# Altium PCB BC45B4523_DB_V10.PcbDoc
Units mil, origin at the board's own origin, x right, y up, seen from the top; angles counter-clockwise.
Board outline 5409.03 x 2550.03 mil, 2 copper layers (Top Layer, Bottom Layer), stack 62.8 mil thick; 96 components, 59 nets, 275 pads, 147 vias.
Unrouted connection lines stored in the file: 1.
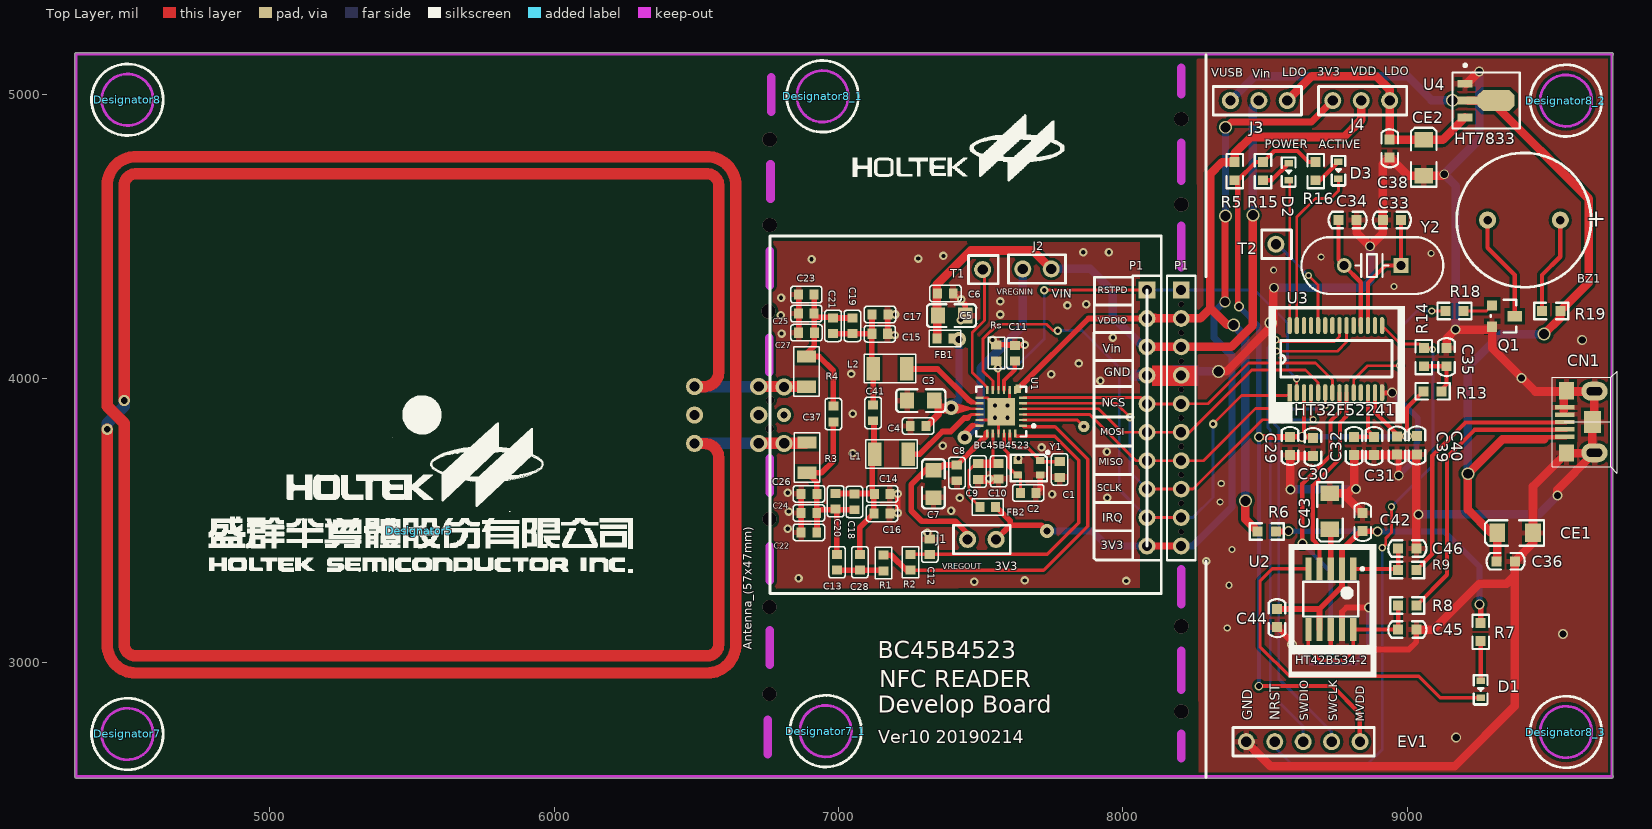
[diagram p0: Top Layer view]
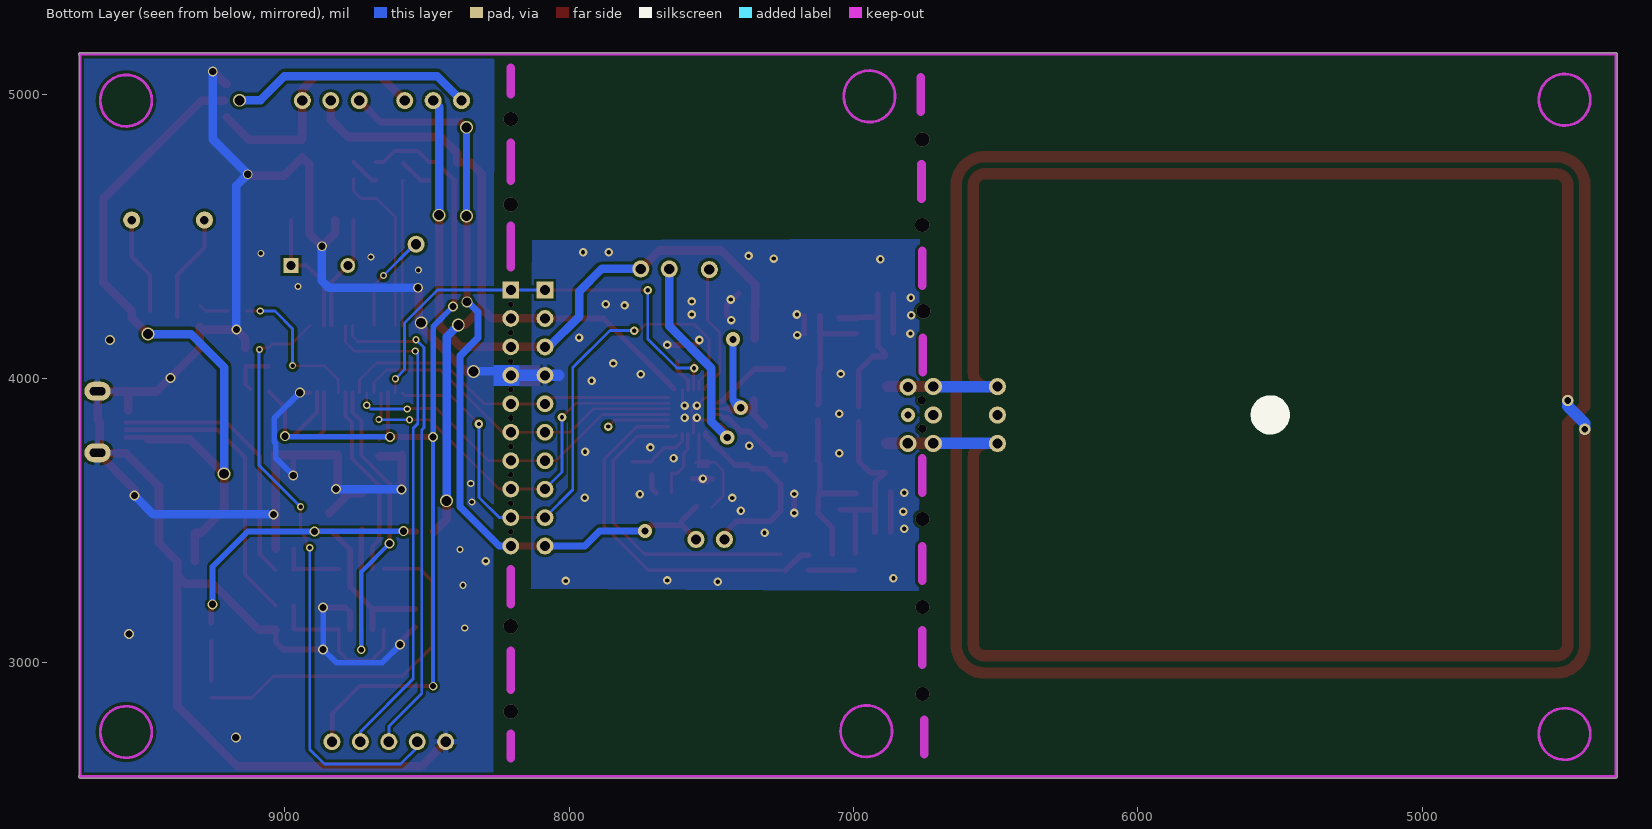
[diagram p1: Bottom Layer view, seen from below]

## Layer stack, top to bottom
Top Layer: signal copper 1.4
Dielectric: core 60, FR-4, Dk 4.6
Bottom Layer: signal copper 1.4

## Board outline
4314.98,2600 ccw(c4320,2600) 4320,2594.99 9719,2594.99 ccw(c9719,2600) 9724.01,2600 ccw(c9719,2600) 9723.01,2603.01 9723.01,5136.99 ccw(c9719,5140) 9724.01,5140 ccw(c9719,5140) 9719,5145.02 4320,5145.02 ccw(c4320,5140) 4314.98,5140

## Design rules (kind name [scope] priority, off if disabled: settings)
Clearance [All] p1: gap=10
Clearance Clearance_Polygon [All vs (InPolygon)] p2: gap=12
Clearance Clearance_Board_Keepout [OnLayer('KeepOutLayer')] p3: gap=20
Clearance Minimum_pad_component_clearcance [(InPadClass('All Pads') AND InComponentClass('All Components')) vs (InPadClass('All Pads') AND InComponentClass('All Components'))] p4: gap=8
Clearance Clearance_DiffPairRouting [(IsTrack AND InDifferentialPairClass('All Differential Pairs')) vs (IsTrack AND InDifferentialPairClass('All Differential Pairs'))] p5: gap=4
Clearance Clearance_Via_Pad [(IsVia) vs (IsPad)] p6: gap=8
Clearance Clearance_Via_Via [(IsVia) vs (IsVia)] p7: gap=8
Clearance Clearance_Default [All] p8: gap=4
ComponentClearance ComponentClearance_1 [All] p2: gap=10 collisioncheckmode=3 verticalgap=10 showdistances=FALSE
DiffPairsRouting DiffPairsRouting_1 [All] p2: maxlimit=10 minlimit=5 mostfreqgap=8 maxuncoupledlength=500
FabricationTestPointUsage FabricationTestPointUsage_1 [All] p2: valid=0 allowmultiple=FALSE
FabricationTestpoint [(IsPad And (OnTopLayer Or OnBottomLayer))] p1: side=3 testpointundercomponent=TRUE minsize=40 maxsize=100 preferedsize=60 minholesize=0 maxholesize=40 preferedholesize=32 testpointgrid=1 allowsidetop=TRUE allowsidebottom=TRUE usegrid=TRUE gridtolerance=0.01
FabricationTestpoint FabricationTestpoint_1 [(IsPad And (OnTopLayer Or OnBottomLayer))] p2: side=3 testpointundercomponent=TRUE minsize=40 maxsize=100 preferedsize=60 minholesize=0 maxholesize=40 preferedholesize=32 testpointgrid=1 allowsidetop=TRUE allowsidebottom=TRUE usegrid=TRUE gridtolerance=0.01
FanoutControl Fanout_LCC [IsLCC] p1: bgadir=Out bgaviamode=Centered fanoutstyle=Auto fanoutdirection=Alternating viagrid=1 // Fanout_LCC (Default Rule)
FanoutControl Fanout_BGA [IsBGA] p2: bgadir=Out bgaviamode=Centered fanoutstyle=Auto fanoutdirection=Alternating viagrid=1 // Fanout_BGA (Default Rule)
FanoutControl Fanout_Default [All] p4: bgadir=Out bgaviamode=Centered fanoutstyle=Auto fanoutdirection=Alternating viagrid=1 // Fanout_Default (Default Rule)
FanoutControl Fanout_Small [(CompPinCount < 5)] p5: bgadir=Out bgaviamode=Centered fanoutstyle=Auto fanoutdirection=OutThenIn viagrid=1 // Fanout_Small (Default Rule)
FanoutControl Fanout_BGA_1 [IsBGA] p6: bgadir=Out bgaviamode=Centered fanoutstyle=Auto fanoutdirection=Alternating viagrid=1 // Fanout_BGA (Default Rule)
FanoutControl Fanout_LCC_1 [IsLCC] p7: bgadir=Out bgaviamode=Centered fanoutstyle=Auto fanoutdirection=Alternating viagrid=1 // Fanout_LCC (Default Rule)
FanoutControl Fanout_SOIC_1 [IsSOIC] p8: bgadir=Out bgaviamode=Centered fanoutstyle=Auto fanoutdirection=Alternating viagrid=1 // Fanout_SOIC (Default Rule)
FanoutControl Fanout_Small_1 [(CompPinCount < 5)] p9: bgadir=Out bgaviamode=Centered fanoutstyle=Auto fanoutdirection=OutThenIn viagrid=1 // Fanout_Small (Default Rule)
FanoutControl Fanout_Default_1 [All] p10: bgadir=Out bgaviamode=Centered fanoutstyle=Auto fanoutdirection=Alternating viagrid=1 // Fanout_Default (Default Rule)
Height Height_1 [All] p2: minheight=0 maxheight=1000 prefheight=500
HoleSize HoleSize_1 [All] p2: absolutevalues=TRUE maxlimit=236.22 minlimit=8 maxpercent=80.000 minpercent=20.000
LayerPairs LayerPairs_1 [All] p2: enforce=TRUE
MinimumAnnularRing [All] p1: minimumring=5
PasteMaskExpansion PasteMaskExpansion_1 [All] p2: expansion=0
PlaneClearance PlaneClearance_1 [All] p2: clearance=10
PlaneConnect PlaneConnect_1 [All] p2: planeconnectstyle=Relief reliefexpansion=20 reliefentries=4 reliefconductorwidth=10 reliefairgap=10
PolygonConnect [IsVia] p1: connectstyle=Direct reliefconductorwidth=10 reliefentries=4 polygonreliefangle="90 Angle" airgapwidth=10
PolygonConnect PolygonConnect_Power [All] p2: connectstyle=Relief reliefconductorwidth=20 reliefentries=4 polygonreliefangle="90 Angle" airgapwidth=10
RoutingCorners RoutingCorners_1 [All] p2: cornerstyle=45-Degree minsetback=100 maxsetback=100
RoutingLayers RoutingLayers_1 [All] p2: top layer_v5=TRUE bottom layer_v5=TRUE
RoutingPriority RoutingPriority_Power [InNetClass('Power')] p2: routingpriority=50
RoutingPriority RoutingPriority_1 [All] p3: routingpriority=0
RoutingTopology RoutingTopology_1 [All] p2: topology=Shortest
RoutingVias [All] p1: holewidth=28 width=50 viastyle="Through Hole" minholewidth=15 minwidth=20 maxholewidth=50 maxwidth=60
RoutingVias RoutingVias_1 [All] p2: holewidth=12 width=22 viastyle="Through Hole" minholewidth=8 minwidth=18 maxholewidth=28 maxwidth=50
ShortCircuit ShortCircuit_1 [All] p2: allowed=FALSE
SilkscreenOverComponentPads [All] p1: minsilkscreentomaskgap=10
SolderMaskExpansion [All] p1: expansion=4
SolderMaskExpansion SolderMaskExpansion_1 [All] p2: expansion=5
UnRoutedNet UnRoutedNet_1 [All] p2:
Width [All] p1: maxlimit=40 minlimit=10 preferedwidth=10 minimp=50.000000 maximp=50.000000 favimp=50.000000
Width Width_Power [InNetClass('Power')] p2: maxlimit=30 minlimit=6 preferedwidth=30
Width Width_All [All] p3: maxlimit=50 minlimit=4 preferedwidth=7 minimp=50.000000 maximp=50.000000 favimp=50.000000
22 further rules are at their usual default settings.

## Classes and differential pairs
component class BC45B4523_DB_Schematic: C1 C2 C3 C4 C5 C6 C7 C8 C9 C10 C11 C12 C13 C14 C15 C16 C17 C18 C19 C20 C21 C22 C23 C24 C25 C26 C27 C28 C37 C41 FB1 FB2 J1 J2 L1 L2 P1 R1 R2 R3 R4 Rs T1 U1 Y1
component class HT32F52241+HT42B534-2: BZ1 C31 C32 C33 C34 C35 C36 C38 C39 C40 C42 C43 C44 C45 C46 CE1 CE2 D1 D2 D3 EV1 J3 J4 Q1 R5 R6 R7 R8 R9 R13 R14 R15 R16 R18 R19 T2 U2 U3 U4 Y2

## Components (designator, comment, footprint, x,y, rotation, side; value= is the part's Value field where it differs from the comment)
BZ1 "Buzzer" BZ 9538,4557 r180 top
C1 "Capacitor SMD" CAPC1608L 7778,3680 r270 top
C2 "Capacitor SMD" CAPC1608L 7667,3598 r0 top
C3 "Capacitor SMD" C0805-2 7343,3922 r180 top
C4 "Capacitor SMD" CAPC1608L 7280,3833 r180 top
C5 "Capacitor SMD" C0805-2 7344,4221 r0 top
C6 "Capacitor SMD" CAPC1608L 7376,4299 r0 top
C7 "Capacitor SMD" C0805-2 7334,3683 r270 top (schematic designator C5)
C8 "Capacitor SMD" CAPC1608L 7416,3668 r270 top (schematic designator C6)
C9 "Capacitor SMD" CAPC1608L 7491.41,3672.93 r270 top
C10 "Capacitor SMD" CAPC1608L 7563.09,3673.92 r270 top
C11 "Capacitor SMD" CAPC1608L 7620.15,4088.65 r90 top
C12 "" CAPC1608L 7321,3408 r270 top
C13 "" CAPC1608L 6995,3354 r270 top
C14 "" CAPC1608L 7153.55,3594 r180 top
C15 "" CAPC1608L 7145.51,4157.15 r0 top
C16 "" CAPC1608L 7153,3526 r180 top
C17 "" CAPC1608L 7146,4225 r0 top
C18 "" CAPC1608L 7056,3566 r270 top
C19 "" CAPC1608L 7049,4185 r90 top
C20 "" CAPC1608L 6990.15,3568 r270 top
C21 "" CAPC1608L 6981,4185 r90 top
C22 "" CAPC1608L 6896,3459 r180 top
C23 "" CAPC1608L 6887,4295 r0 top
C24 "" CAPC1608L 6896,3527 r180 top
C25 "" CAPC1608L 6887,4228 r0 top
C26 "" CAPC1608L 6896.3,3594.43 r0 top
C27 "" CAPC1608L 6887.5,4160.9 r180 top
C28 "" CAPC1608L 7075,3354 r270 top
C29 "0.1uF" C0603-2 8588,3795 r270 top
C30 "" C0603-2 8668,3727 r90 top
C31 "0.1uF(NC)" C0603-2 8883,3795 r270 top
C32 "2.2uF" C0603-2 8813,3795 r270 top
C33 "12pF" C0603-2 8978,4557 r180 top
C34 "12pF" C0603-2 8758,4557 r0 top
C35 "0.1uF" C0603-2 9138,4043 r90 top
C36 "0.1uF" C0603-2 9378,3357 r180 top
C37 "" CAPC1608L 6982,3875 r90 top (schematic designator C19)
C38 "0.1uF" C0603-2 8938,4777 r90 top (schematic designator C36)
C39 "" C0603-2 8964,3732 r90 top (schematic designator C30)
C40 "0.1uF" C0603-2 9034,3797 r270 top (schematic designator C29)
C41 "" CAPC1608L 7122,3879 r270 top (schematic designator C19)
C42 "0.1uF" C0603-2 8843,3463 r90 top
C43 "1uF" C_CASE_A 8728,3472 r90 top
C44 "0.1uF" C0603-2 8542,3189.63 r270 top
C45 "47pF" C0603-2 8968,3117 r0 top
C46 "47pF" C0603-2 8968,3402 r0 top
CE1 "1uF" C_CASE_A 9318,3457 r0 top
CE2 "10uF" C_CASE_A 9058,4837 r270 top (schematic designator CE1)
CN1 "Comment" M-USB-B 9715,3847 r90 top
D1 "LED" LED_SMD0603 9258,2937 r270 top
D2 "Power/RLED" LED_SMD0603 8583,4757 r270 top
D3 "GLED" LED_SMD0603 8758,4762 r270 top
Designator5 "Comment" HOLTEK_MARK 5526,3465 r0 top
Designator7 "Comment" VIA_HOLD2 4500,2750 r0 top
Designator7_1 "Comment" VIA_HOLD2 6955,2760 r0 top
Designator8 "Comment" VIA_HOLD2 4500,4980 r0 top
Designator8_1 "Comment" VIA_HOLD2 6944,4992 r0 top
Designator8_2 "Comment" VIA_HOLD2 9558,4977 r0 top
Designator8_3 "Comment" VIA_HOLD2 9558,2757 r0 top
EV1 "*" CON5 8834,2723 r180 top
FB1 "Ferrite Bead" INDC1608L 7374.76,4140.7 r180 top
FB2 "Ferrite Bead" INDC1608L 7525,3548 r180 top
J1 "SB2" CON2 7454,3434 r0 top
J2 "SB1" CON2 7648,4385 r0 top
J3 "SB4" CON3 8578,4977 r180 top
J4 "SB4" CON3 8738,4977 r0 top
L1 "470nH" 2029 7186,3734 r0 top
L2 "470nH" 2029 7181,4035 r0 top
P1 "Header 10" HDR1x10 8084.75,4310.86 r270 top
P1 "Header 10" HDR1x10 8205,4311 r270 top
Q1 "8050" SOT-23 9298,4257 r270 top
R1 "" INDC1608L 7158,3351 r90 top
R2 "" INDC1608L 7252.95,3353.49 r90 top
R3 "Resistor SMD" RESC3216L 6889.31,3721.54 r270 top
R4 "Resistor SMD" RESC3216L 6888,4024 r90 top
R5 "0" R0603-2 8393,4697 r90 top
R6 "0" R0603-2 8538,3462 r180 top
R7 "330" R0603-2 9258,3077 r90 top
R8 "33" R0603-2 8968,3202 r0 top
R9 "33" R0603-2 8968,3327 r0 top
R13 "100K" R0603-2 9057,3955 r0 top
R14 "300" R0603-2 9058,4043 r90 top
R15 "300" R0603-2 8493,4697 r90 top
R16 "300" R0603-2 8678,4697 r90 top
R18 "4.7K" R0603-2 9198,4237 r180 top (schematic designator R7)
R19 "100" R0603-2 9538,4237 r180 top (schematic designator R7)
Rs "Res3" INDC1608L 7554.78,4089.49 r270 top
T1 "ICP" CON1 7507,4383 r0 top
T2 "CON1" CON1 8538,4472 r0 top
U1 "BC45B4523" QFN50P400X400X100-24L 7572.32,3883.23 r180 top
U2 "HT42B534-2" 10SOP 8731,3224 r270 top
U3 "HT32F52241" SSOP28_150 8749,4068 r90 top
U4 "HT7833" SOT89 9258,4977 r270 top (schematic designator U3)
Y1 "XTAL" XSM-B2 7670,3686 r180 top
Y2 "16MHz" XTAL_B 8978,4397 r180 top

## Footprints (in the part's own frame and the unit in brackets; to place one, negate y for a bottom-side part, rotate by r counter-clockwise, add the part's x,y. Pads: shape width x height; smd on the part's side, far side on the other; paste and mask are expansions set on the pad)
10SOP [mm] "SOP, 10-Leads, Body 4.90x3.90mm, Pitch 1.00mm, IPC Medium Density"
  rect 2.032x0.55 smd: 1(-2.7,2) 2(-2.7,1) 3(-2.7,0) 4(-2.7,-1) 5(-2.7,-2) 6(2.7,-2) 7(2.7,-1) 8(2.7,0) 9(2.7,1) 10(2.7,2)
  silkscreen extent -2.82,-2.45 1.55,2.95, body extent -1.91,-2.49 1.99,2.41, height 1.75
2029 [mm] "Chip Inductor, Body 2.0x1.2mm, IPC High Density"
  rect 1.2x2.1 smd: 1(-1.5,0) 2(1.5,0)
  silkscreen extent -2.29,-1.27 2.31,1.27, body extent -1.1,-1.07 1.1,1.09, height 0.55
BZ [mil]
  round 60 hole 30: 1(0,0) 2(255.91,0)
  silkscreen extent -108,-236 364,236
C0603-2 [mil]
  rect 35x35 smd: 1(0,0) 2(64,0)
  silkscreen extent -35,-29 99,29
C0805-2 [mil]
  rect 50x56 smd: 1(6,0) 2(102,0)
  silkscreen extent -33,-40 140,40
C_CASE_A [mil]
  rect 55x65 smd: 1(-2,0) 2(124,0)
  silkscreen extent -45,-45 163,45
CAPC1608L [mm] "Chip Capacitor, Body 1.6x0.8mm, IPC High Density"
  rect 0.8x0.9 smd: 1(-0.7,0) 2(0.7,0)
  silkscreen extent -1.4,-0.74 1.4,0.74, body extent -0.79,-0.41 0.81,0.39, height 0.78
CON1 [mil]
  round 60 hole 36: 1(0,0)
  silkscreen extent -50,-50 55,50
CON2 [mil]
  round 60 hole 36: 1(0,0) 2(100,0)
  silkscreen extent -50,-50 150,50
CON3 [mil]
  round 60 hole 36: 1(0,0) 2(100,0) 3(200,0)
  silkscreen extent -50,-50 260,50
CON5 [mil]
  round 60 hole 36: 1(0,0) 2(100,0) 3(200,0) 4(300,0) 5(400,0)
  silkscreen extent -50,-50 447,50
HDR1x10 [mm] "Connector; Header;"
  rect 1.5x1.5 hole 0.9: 1(0,0)
  round 1.5 hole 0.9: 2(2.54,0) 3(5.08,0) 4(7.62,0) 5(10.16,0) 6(12.7,0) 7(15.24,0) 8(17.78,0) 9(20.32,0) 9(22.86,0)
  silkscreen extent -1.27,-1.27 24.13,1.27
HOLTEK_MARK [mil]
  silkscreen extent -740,-146 750,380
INDC1608L [mm] "Chip Inductor, Body 1.6x0.8mm, IPC High Density"
  rect 0.8x0.9 smd: 1(-0.7,0) 2(0.7,0)
  silkscreen extent -1.4,-0.74 1.4,0.74, body extent -0.76,-0.43 0.79,0.42, height 0.44
LED_SMD0603 [mil]
  rect 23x30 smd: 1(0,0) 2(60,0)
  silkscreen extent -20,-24 83,24
M-USB-B [mm]
  rect 1.55x1.35 smd: 0(-2.775,3.95) 0(2.775,3.95)
  oval 1.7x2.35 hole 0.75 slot 1.4 at 90 deg: 0(-2.75,1.45) 0(2.75,1.45)
  rect 2x1.5 smd: 0(0,1.626)
  rect 0.4x1.7 smd: 1(-1.3,4.1) 2(-0.65,4.1) 3(0,4.1) 4(0.65,4.1) 5(1.3,4.1)
  silkscreen extent -4.58,-0.58 4.53,5.23
QFN50P400X400X100-24L [mm] "QFN, 24-Leads, Body 4.00x4.00mm, Pitch 0.50mm, IPC High Density"
  rect 0.7x0.2 smd: 1(-1.95,1.25) 2(-1.95,0.75) 3(-1.95,0.25) 4(-1.95,-0.25) 5(-1.95,-0.75) 6(-1.95,-1.25) 13(1.95,-1.25) 14(1.95,-0.75) 15(1.95,-0.25) 16(1.95,0.25) 17(1.95,0.75) 18(1.95,1.25)
  rect 0.2x0.7 smd: 7(-1.25,-1.95) 8(-0.75,-1.95) 9(-0.25,-1.95) 10(0.25,-1.95) 11(0.75,-1.95) 12(1.25,-1.95) 19(1.25,1.95) 20(0.75,1.95) 21(0.25,1.95) 22(-0.25,1.95) 23(-0.75,1.95) 24(-1.25,1.95)
  rect 2.489x2.489 smd: 25(0,0)
  silkscreen extent -3.02,-2.22 2.22,2.23, body extent -2,-2 2,2.01, height 0.9
R0603-2 [mil]
  rect 35x35 smd: 1(0,0) 2(64,0)
  silkscreen extent -28,-29 92,29
RESC3216L [mm]
  rect 1.1x1.7 smd: 1(-1.35,0) 2(1.35,0)
  silkscreen extent -2.21,-1.14 2.21,1.14, body extent -1.6,-0.81 1.6,0.79, height 0.55
SOT89 [mm] "SOT-89; Body 4.6 x 4.25 mm, inc. leads (LxW max)"
  oct 1.9x3.3 smd: 0(0,1.388)
  rect 0.7x1.35 smd: 1(-1.5,-1.388) 3(1.5,-1.388)
  rect 0.7x1.8 smd: 2(0,-1.162)
  silkscreen extent -3.27,-2.51 2.5,3.49
SOT-23 [mil]
  rect 36x50 smd: 1(38,80)
  rect 36x36 smd: 2(0,0) 3(75,0)
  silkscreen extent -20,-5 95,85
SSOP28_150 [mil]
  rect 60x15 smd: 1(-118.11,162.5)
  oval 60x15 smd: 2(-118.11,137.5) 3(-118.11,112.5) 4(-118.11,87.5) 5(-118.11,62.5) 6(-118.11,37.5) 7(-118.11,12.5) 8(-118.11,-12.5) 9(-118.11,-37.5) 10(-118.11,-62.5) 11(-118.11,-87.5) 12(-118.11,-112.5) 13(-118.11,-137.5) 14(-118.11,-162.5) 15(118.11,-162.5) 16(118.11,-137.5) 17(118.11,-112.5) 18(118.11,-87.5) 19(118.11,-62.5) 20(118.11,-37.5) 21(118.11,-12.5) 22(118.11,12.5) 23(118.11,37.5) 24(118.11,62.5) 25(118.11,87.5) 26(118.11,112.5) 27(118.11,137.5) 28(118.11,162.5)
  silkscreen extent -63,-197 65,194
VIA_HOLD2 [mil]
  Keep-Out Layer circle w10: c0.02,0 r90.55
  silkscreen extent -126,-126 126,126
XSM-B2 [mm] "Crystal; Surface-mounh; 4 Leads; 1.6x1.2 mm"
  rect 0.75x0.6 smd: 1(-1,-0.65) 2(1,0.65) 3(-1,0.65) 3(1,-0.65)
  silkscreen extent -1.8,-1.5 1.63,1.19
XTAL_B [mil]
  rect 52x52 hole 31: 1(0,0)
  round 52 hole 31: 2(200,0)
  silkscreen extent -149,-100 350,100

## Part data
C1 C2 C3 C4 C5 C6 C7 C8 C9 C10 C11: "Capacitor Surface Mount (SIM Model)"
C12 C13 C14 C15 C16 C17 C18 C19 C20 C21 C22 C23 C24 C25 C26 C27 C28 C30 C37 C39 C41: library part "Cap Semi", "Capacitor (Semiconductor SIM Model)"
C29 C31 C32 C33 C34 C40: library part Cap, "Capacitor"
C35 C36 C38: library part CAP, "Capacitor"
C42 C44 C45 C46: library part CAP_NP, "Capacitor"
C43: library part "CAP POL", "Capacitor"
CE1 CE2: library part CAP1_POLARITY, "Electrolytic Capacitor"
D2 D3: library part LED
EV1: library part CON5
J3 J4: library part "Header 3", "Header, 3-Pin"
L1 L2: library part Inductor, "Inductor"
R1 R2: library part Res3, "Resistor"
R3 R4: "Resistor Surface Mount"
R5 R6 R7 R8 R9 R13 R14 R15 R16 R18 R19: library part R_1/4W
Rs: "Resistor"
T1: library part "Header 1", "Header, 1"
U1: library part SICRA12, "RFID Reader IC"
U2: library part BCM7602
U3: library part HT32F52241_28SSOP
U4: library part LDO
Y1: library part XTAL_2, "Crystal Oscillator"
Y2: library part XTAL, "Crystal Oscillator"

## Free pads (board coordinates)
  round 100 hole 100: 0(5534.8,3871.99)
  round 40 hole 24: 1(4428.8,3821.49) 1(4488.8,3922.49)
  round 60 hole 36: 1(6493.8,3771.49) 1(6493.8,3871.49) 1(6493.8,3971.49)
  rect 20x30 smd: 7(7632.3,3964.31)
  round 40 smd: 10(7862.69,3831.08)

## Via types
v1: diameter 30, hole 15, Top Layer to Bottom Layer, tented both sides, 50 vias
v2: diameter 35, hole 25, Top Layer to Bottom Layer, tented both sides, 26 vias
v3: diameter 25, hole 15, Top Layer to Bottom Layer, tented both sides, 22 vias
v4: diameter 50, hole 50, Top Layer to Bottom Layer, tented both sides, 10 vias
v5: diameter 45, hole 35, Top Layer to Bottom Layer, tented both sides, 10 vias
v6: diameter 20, hole 20, Top Layer to Bottom Layer, tented both sides, 9 vias
v7: diameter 60, hole 36, Top Layer to Bottom Layer, 5 vias
v8: diameter 30, hole 15, Top Layer to Bottom Layer, 4 vias
v9: diameter 50, hole 25, Top Layer to Bottom Layer, tented both sides, 4 vias
v10: diameter 30, hole 20, Top Layer to Bottom Layer, tented both sides, 2 vias
v11: diameter 30, hole 30, Top Layer to Bottom Layer, tented both sides, 2 vias
v12: diameter 50, hole 25, Top Layer to Bottom Layer, 1 vias
v13: diameter 30, hole 15, Top Layer to Bottom Layer, tented top, 1 vias
v14: diameter 40, hole 30, Top Layer to Bottom Layer, tented both sides, 1 vias

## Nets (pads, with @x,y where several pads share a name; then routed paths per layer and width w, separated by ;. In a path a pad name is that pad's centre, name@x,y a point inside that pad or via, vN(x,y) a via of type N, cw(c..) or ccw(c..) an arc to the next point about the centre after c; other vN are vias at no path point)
+3.3V: FB2.1 J1.2 J4.1 P1.9@8084.75,3410.86 P1.9@8205,3411 | length 2816
  Top Layer w20: FB2.1 7552.83,3548.27 7555,3548.27 7604,3499.27 7604,3484 ; J1.2 7604,3484 ; v9(7733,3463.9) 7712.9,3484 7604,3484
  Top Layer w25: P1.9@8084.75,3410.86 P1.9@8204.86,3410.86 ; v14(8359,4269) 8359,4569 v5(8361,4571) ; v5(8361,4883) 8380,4902 8663,4902 J4.1
  Bottom Layer w25: v9(7733,3463.9) 7892.1,3463.9 7945.14,3410.86 P1.9@8084.75,3410.86 ; P1.9@8205,3411 8245.89,3411 8383,3548.11 8383,4080 8320,4143 8320,4234 v14@8355,4269 ; v5(8361,4571) v5(8361,4883)
AVDD: C9.1 C10.1 FB2.2 U1.20 | length 356.2
  Top Layer w10: FB2.2 7458,3587.44 7458,3676.83 7486.54,3705.37 C9.1@7500.84,3705.37 ; C9.1@7500.84,3704.82 7543.43,3704.82 ; U1.20 7542.79,3705.45 7543.43,3704.82 ; C10.1@7555.31,3704.82 7543.43,3704.82
BG_RX: U2.8 U3.8 | length 1071.1
  Top Layer w15: v2(8631,3420) 8631,3630 8730,3729 8730,3850 8761.5,3881.5 U3.8 ; v10(8731,3046) U2.8
  Bottom Layer w15: v2(8631,3420) 8731,3320 v10(8731,3046)
BG_TX: U2.4 U3.9 | length 678.5
  Top Layer w15: U2.4 8691.63,3409.37 8668,3433 8668,3624 8763,3719 8763,3844 8786.5,3867.5 U3.9
BUZZER: R18.2 U3.10 | length 544.9
  Top Layer w10: U3.10 8811.5,3996.5 8860,4045 v3(8972,4045) ; v3(9086,4237) R18.2
  Bottom Layer w10: v3(8972,4045) 8972,4175 9034,4237 v3(9086,4237)
BVDD: C42.1 C44.1 R6.1 R7.2 U2.2 U2.7 | length 1586.2
  Top Layer w20: R6.1 8583,3462 v2@8584,3463 ; C44.1 8691.63,3189.63 ; U2.7 8691.63,3189.63 ; v2@8896,3463 C42.1 8835,3463 8770.37,3398.37 U2.2 8770.37,3268.37 8691.63,3189.63 ; v2(9254,3206) 9258,3202 R7.2
  Bottom Layer w20: v2(8582,3463) 8896,3463 v2@8897,3462 ; v2(8895,3462) v2@8897,3462 ; v2(9254,3206) 9254,3338 9130,3462 v2@8897,3462
CLDO: C31.1 C32.1 U3.12 | length 233.8
  Top Layer w15: C32.1 C31.1 8861.5,3816.5 U3.12
D+: C46.1 R9.1 U2.1 | length 234.6
  Top Layer w15: U2.1 8964.7,3330.3 R9.1 C46.1
D-: C45.1 R8.1 U2.6 U2.10 | length 574
  Top Layer w12: U2.6 8652.26,3050.74 8693,3010 8778,3010 8809.74,3041.74 U2.10
  Top Layer w15: U2.10 8967.3,3117.7 C45.1 R8.1
DVDD: C11.1 U1.9 | length 116.5
  Top Layer w15: U1.9@7582.15,3960.31 7582.15,3992.75 7620.11,4030.7 C11.1
F_NRST: EV1.4 R14.2 U3.15 | length 2136
  Top Layer w10: U3.15 8976.61,4121 9044,4121 R14.2 9084,4107 v3(9089,4102) ; v3(8912,3405) 8924,3417 8924,3438 8944,3458 v3(8944,3549)
  Bottom Layer w10: EV1.4 8534,2703 8593,2644 8860,2644 8912,2696 v3(8912,3405) ; v3(8944,3549) 9090,3695 v3@9090,4102
GLED: D3.2 U3.27 | length 608.2
  Top Layer w10: U3.27 8611.5,4567.5 8677,4633 8731,4633 8758,4660 D3.2
GND: C1.2 C2.2 C3.2 C4.2 C5.2 C6.2 C7.2 C8.2 C9.2 C10.2 C11.2 C12.1 C14.1 C15.2 C16.1 C17.2 C22.2 C23.1 C24.2 C25.1 C26.1 C27.2 C29.2 C30.1 C31.2 C32.2 C33.2 C34.2 C35.2 C36.1 C38.1 C39.1 C40.2 C42.2 C43.2 C44.2 C45.2 C46.2 CE1.2 CE2.2 CN1.0 CN1.4 CN1.5 EV1.5 P1.4 Q1.3 Rs.1 U1.8 U1.13 U1.17 U1.21 U1.25 U2.9 U3.14 U4.1 Y1.3 | length 10820.8
  Top Layer w10: U1.17@7495.53,3854.01 U1.25@7542.78,3854.01 ; U1.13 7523.1,3932.45 v8(7550.66,3904.89) U1.25 ; U1.21 U1.25@7562.47,3873.39 ; U1.25@7601.83,3913.07 U1.8@7601.83,3960.31
  Top Layer w15: U3.14 8946.89,3949.89 v2(8947,3950)
  Top Layer w20: C27.2 C23.1@6859.94,4295 ; C22.2@6868.74,3459 C26.1@6868.74,3601 ; C15.2 C17.2@7173.06,4220.25 ; v1@7208.55,3532.3 v1(7208.55,3594) ; C6.2 7426.56,4276 7429,4276 7446,4259 C5.2 ; C9.2@7494.57,3647.44 C10.2@7564.46,3647.44 ; Rs.1@7541.71,4132.09 v1(7541.71,4135.3) ; Rs.1@7554.78,4119.02 C11.2@7617.34,4119.02 ; 7591.06,4117.99 v1(7654.75,4117.99) ; C11.2@7615.18,4116.21 C11.2 ; C2.2 7709.37,3612.81 Y1.3@7709.37,3660.41 ; C44.2 8594,3073.63 v2(8594,3064) ; U2.9 8770.37,3179.37 8786,3195 v2(8865,3195) ; v2(8865,3047) 9005,3047 9032,3074 C45.2 ; C39.1 8965,3731 8970,3726 v2(8970,3659)
  Top Layer w30: v5(8336,4025) 8364,4025 8528,4189 v2@8528,4307 ; EV1.5@8433,2723 8520,2636 9166,2636 9378,2848 9378,3307 ; v2@8588,3611 C29.2 ; C29.2@8592,3727 C30.1 ; C43.2 8774,3596 ; v2@8813,3618 C32.2 C31.2 8965,3731 C40.2@9032,3731 ; v2(8820,3611) 8806,3611 8791,3596 8774,3596 ; C34.2 8822,4512 v2(8869,4465) 8914,4510 C33.2 8914,4753 C38.1 9002,4713 CE2.2 9125,4713 v2(9130,4718) ; C42.2 8774,3596 ; C45.2 9092,3117 9254,3279 9350,3279 9378,3307 ; C46.2 C40.2@9032,3731 ; C40.2 C40.2@9032,3731 ; C35.2 9138,4140 v2(9170,4172) 9288,4172 Q1.3 9298,4107 9450.75,3954.25 CN1.0@9557.49,3954.25 ; U4.1 9209.06,5036.06 v2(9253,5080) ; v2(9528,3588) 9528,3608.82 CN1.0@9656.93,3737.75 ; 9549.65,3887 9549.65,3946.41 CN1.0@9557.49,3954.25 ; CN1.0@9559.49,3956.25 CN1.0@9557.49,3954.25 ; CN1.0@9657.91,3955.27 CN1.0@9657.91,3954.25 ; 9378,3307 C36.1 9442,3421 CE1.2 9442,3620.26 9559.49,3737.75 CN1.0@9656.93,3737.75 ; CN1.0@9557.49,3954.25 CN1.0@9657.91,3954.25 ; CN1.0@9656.93,3737.75 9657.91,3738.73 9651,3745.65 9651,3847 9657.91,3853.91 CN1.0@9657.91,3954.25
  Bottom Layer w20: v2(8594,3064) 8657,3001 8819,3001 v2(8865,3047) v2(8865,3195) ; v2(8947,3950) 9036.5,3860.5 9036.5,3776.97 9032,3772.47 9032,3721 v2(8970,3659)
  Bottom Layer w30: 8244,4012 8257,4025 v5(8336,4025) ; v2(8532,4319) 8845,4319 8869,4343 v2(8869,4465) ; v2@8592,3611 v2(8820,3611) ; v2(9039,3522) 9462,3522 v2(9528,3588) ; v2(9170,4172) 9170,4678 v2(9130,4718) 9253,4841 v2(9253,5080)
  Bottom Layer w40: 8036.14,4010.86 8084.75,4010.86 P1.4@8204.86,4010.86
  other v1: 7477,3285 8012.04,3287.99 7655,3290 6859.58,3297.17 8292.75,3357.86 7312.66,3457.46 6822,3472 7208.55,3527 6825,3532 7396,3535 7426,3580 7945,3581 7750.97,3593.19 6821.85,3598.17 7529.45,3648.08 7632.65,3719.73 7050,3737 7944,3742 7714.11,3757.41 7366.69,3763.58 7050,3876 7921,3992 7748.59,4014.84 7045,4016 7845,4053 7965,4144 7197.5,4152.68 6800,4158 7430.05,4205.22 6797,4222 7199,4225 7569,4225 7805,4257 7871,4261 7569,4271 7431.39,4277.68 6798,4284 6905.43,4419.33 7280.14,4421.57 7369,4431 7861,4444 7951,4444
  other v2: 9172,2738 9548,3102 8590,3609 9401,4002 9615,4135
  other v3: 8367,3123 8373,3273 8384,3399 8342,3566 8346,3631 8953,4323 8530,4381 8697,4427 9084,4440
  other v5: 8520,4196
  other v8: 7550.66,3861.58 7593.97,3861.58 7593.97,3904.89
HXTI: C34.1 U3.18 Y2.2 | length 403.4
  Top Layer w15: C34.1 8758,4417 Y2.2 8836.5,4338.5 U3.18
HXTO: C33.1 U3.17 Y2.1 | length 451.4
  Top Layer w15: U3.17 8861.5,4335.5 8923,4397 Y2.1 C33.1
IOVDD: J4.2 P1.2 pad.7 R5.2 R6.2 U1.7 | length 2831.5
  Top Layer w20: pad.7 7878.85,4210.86 P1.2@8084.75,4210.86
  Top Layer w30: P1.2@8084.5,4213 8113,4213 8111,4211 8205,4211 8272,4211 8308,4247 ; v5(8389.63,4188.15) 8366.85,4188.15 8308,4247 ; v5(8431,3570) 8431,3505 R6.2 ; J4.2 8838,4910 8777,4849 8450,4849 8393,4792 R5.2 8349,4761 8308,4720 8308,4247
  Bottom Layer w30: v5(8389.63,4188.15) 8431,4146 v5(8431,3570)
IRQ: P1.9@8084.75,3510.86 P1.9@8205,3511 U1.11 U3.1 | length 2157.4
  Top Layer w10: U1.11@7542.78,3960.31 7542.78,3991.22 7508.74,4025.26 7508.74,4139.61 7559.91,4190.78 7731.24,4190.78 7753.87,4168.15 v1(7771,4168.15) ; P1.9@8084.75,3510.86 8204.86,3510.86 P1.9@8205,3511 ; v1(8317,3840) 8417,3940 8576.61,3940 U3.1
  Bottom Layer w10: v1(7771,4168.15) 7856.85,4168.15 7987,4038 7987,3608.61 P1.9@8084.75,3510.86 ; P1.9@8205,3511 8245.89,3511 8317,3582.11 v1@8317,3839
LED: D1.2 U2.5 | length 1268.8
  Top Layer w12: U2.5 8525.3,3330.3 8482,3287 8482,3057 8586,2953 9040,2953 9116,2877 D1.2
MVDD: C29.1 C30.2 C39.2 C40.1 EV1.1 R5.1 R13.1 R15.2 R16.2 U3.3 U3.13 | length 3759.3
  Top Layer w15: R5.1@8404,4697 8468,4761 R15.2 8532,4800 8614,4800 8653,4761 R16.2 ; v10(8478.5,2918.5) 8736.5,2918.5 8833,2822 EV1.1@8833,2723 ; v2@8636.5,3801.5 U3.3 ; U3.13 8886.5,3881.5 8971,3797 v2(8999,3797) 8999,3897 R13.1
  Top Layer w20: R5.1@8404,4697 8404,4257 v2(8408,4253) ; v2(8479,3794) 8587,3794 C29.1 v2(8630,3795) ; v2@8636.5,3801.5 v2(8630,3795) ; C30.2 8664,3795 v2(8630,3795)
  Bottom Layer w15: v10@8478,2917 8479,2918 v2(8479,3794)
  Bottom Layer w20: v2(8408,4253) 8478,4183 v2@8478,3794 ; v2(8630,3795) 9004,3795 v2@9005,3796
NCS/NSS: P1.5 U1.6 U3.7 | length 1225
  Top Layer w10: U1.6@7649.08,3932.75 8062.85,3932.75 8084.75,3910.86 P1.5@8205,3910.86 ; P1.5@8205,3911 8299,3911 8442,4054 8677,4054 8736.5,3994.5 U3.7
NetBZ1_1: BZ1.1 R19.2 | length 346.5
  Top Layer w15: R19.2 9474,4364 9538,4428 BZ1.1
NetBZ1_2: BZ1.2 Q1.1 | length 377.7
  Top Layer w15: BZ1.2 9282.09,4459.91 9378,4364 Q1.1
NetC1_1: C1.1 U1.23 Y1.1 | length 231.2
  Top Layer w12: U1.23@7601.83,3806.77 7601.83,3780.17 7626,3756 7664.96,3756 Y1.1 ; Y1.1@7709.37,3707.56 C1.1
NetC2_1: C2.1 U1.22 Y1.2 | length 244.7
  Top Layer w12: U1.22 7582.16,3751.91 7597,3737.07 7597,3689.25 7619.09,3667.16 7640.04,3667.16 C2.1@7640.04,3598
NetC13_1: C13.1 C18.2 C20.2 C22.1 C24.1 C26.2 C37.1 R3.2 | length 750.5
  Top Layer w20: C24.1@6923.85,3532.34 C24.1@6924.76,3533.25 ; C22.1@6924.76,3459 C24.1@6924.76,3533.25 ; C24.1@6929.76,3533.25 6924,3539.01 6924,3633.7 R3.2 6940.39,3668.39 6982,3710 C37.1 ; C24.1@6930.22,3538.71 C24.1@6924.76,3533.25 ; C24.1@6935.22,3538.71 C20.2@6991.89,3538.71 ; C20.2 C20.2@6991.89,3538.71 ; C13.1@6993.51,3385 6993.51,3537.08 C20.2@6991.89,3538.71 ; C18.2@7046.32,3538.71 C20.2@6991.89,3538.71
NetC14_2: C14.2 C16.2 C18.1 C20.1 C28.1 C41.2 L1.1 | length 588
  Top Layer w20: C20.1 C14.2@7121.56,3595.56 ; C28.1 7075,3476.01 C16.2@7125.99,3527 ; C14.2@7118.44,3594 L1.1@7118.44,3700.07 ; C16.2@7124,3540.59 C14.2@7124,3581.31 ; C41.2@7125,3853.44 7125,3712.95 L1.1@7126.94,3711
NetC15_1: C15.1 C17.1 C19.1 C21.1 C41.1 L2.1 | length 443.4
  Top Layer w20: C21.1@6990.15,4157.34 7117,4157.34 L2.1@7117,4035 ; C15.1@7113.84,4155.41 7117.95,4159.51 C17.1@7117.95,4220.25 ; L2.1 7121.94,3911.61 C41.1@7125,3908.56
NetC19_2: C19.2 C21.2 C23.2 C25.2 C27.1 C37.2 R4.2 | length 575.9
  Top Layer w20: R4.2 6931.85,4077.15 6982,4027 C37.2 ; R4.2@6888.31,4083.69 6888.31,4087.29 6915.06,4114.05 C27.1 C23.2@6915.06,4295 ; C25.2@6925.36,4214.76 C21.2@6980.85,4214.76 ; C21.2@6990.15,4212.46 C19.2@7049,4212.46
NetC35_1: C35.1 R13.2 R14.1 | length 166.6
  Top Layer w15: R14.1 C35.1 9138,3979 R13.2@9122,3963
NetCN1_2: CN1.2 R8.2 | length 1024.3
  Top Layer w15: R8.2 9140,3310 9140,3723 9236.41,3819.41 CN1.2@9558.65,3819.41
NetCN1_3: CN1.3 R9.2 | length 943.3
  Top Layer w15: R9.2 9088,3383 9088,3728 9205,3845 CN1.3@9558.65,3845
NetD1_A: D1.1 R7.1 | length 140
  Top Layer w15: D1.1 R7.1
NetD2_A: D2.1 R15.1 | length 114.9
  Top Layer w15: R15.1 8523,4697 D2.1
NetD3_A: D3.1 R16.1 | length 106.9
  Top Layer w15: R16.1 8693,4697 D3.1
NetQ1_2: Q1.2 R18.1 | length 108.3
  Top Layer w10: R18.1 9278,4237 Q1.2
NetR3_1: pad.1@4428.8,3821.49 pad.1@4488.8,3922.49 pad.1@6493.8,3771.49 pad.1@6493.8,3971.49 R3.1 R4.1 | length 16014.6
  Top Layer w20: v7@6705.71,3780.04 v7@6719.8,3780.04
  Top Layer w40: pad.1@4428.8,3821.49 4428.8,3064.49 ccw(c4528.8,3064.49) 4528.8,2964.49 ; pad.1@4488.8,3922.49 4488.8,4679.49 cw(c4528.8,4679.49) 4528.8,4719.49 6538.8,4719.49 cw(c6538.8,4679.49) 6578.8,4679.49 6578.8,4021.49 cw(c6528.8,4021.49) 6528.8,3971.49 ; 4523.8,2964.49 6538.8,2964.49 ccw(c6538.8,3064.49) 6638.8,3064.49 ; 4523.8,4779.49 6544.8,4779.49 ; 4525.8,3024.49 6538.8,3024.49 ccw(c6538.8,3064.49) 6578.8,3064.49 6578.8,3721.49 ccw(c6528.8,3721.49) 6528.8,3771.49 ; 4528.8,3024.49 cw(c4528.8,3064.49) 4488.8,3064.49 4488.8,3842.49 4428.8,3902.49 4428.8,4679.49 cw(c4528.8,4679.49) 4528.8,4779.49 ; pad.1@6493.8,3771.49 6529.8,3771.49 ; pad.1@6493.8,3971.49 6529.8,3971.49 ; 6638.8,3065.49 6638.8,3871.49 6638.8,4684.49 ; v7(6719.8,3771.99) v7(6809,3771.99) R3.1@6883.78,3771.99 ; v7(6719.8,3971.99) R4.1@6879.96,3971.99
  Bottom Layer w40: pad.1@4428.8,3821.49 4428.8,3842.49 4488.8,3902.49 pad.1@4488.8,3922.49 ; pad.1@6493.8,3771.99 v7(6719.8,3771.99) ; pad.1@6493.8,3970.99 v7@6719.8,3970.99
  other v7: 6808.65,3970.3
RLED: D2.2 U3.28 | length 512.3
  Top Layer w10: D2.2 8586.5,4693.5 U3.28
RSTPD: P1.1 Rs.2 U1.10 U3.2 | length 1629.9
  Top Layer w10: v1(7560.65,4036.26) Rs.2@7560.65,4054.1 ; U1.10 v1@7562.47,4036.26 ; v1@7727.05,4310.86 P1.1@8084.75,4310.86 ; v3(8611,3999) 8611.5,3998.5 U3.2
  Bottom Layer w10: v1(7560.65,4036.26) 7620.97,4036.26 7723.27,4138.56 v1@7723.27,4310.86 ; P1.1@8084.75,4310.86 8463.14,4310.86 8579,4195 8579,4031 v3(8611,3999)
  other v1: 7723.27,4310
RX: C13.2 C28.2 R1.1 | length 161
  Top Layer w20: C13.2@6997,3326.11 7036.15,3326.11 ; 7036.15,3325.94 R1.1@7158,3325.94
RX_: R1.2 R2.1 U1.1 | length 1298.6
  Top Layer w12: R2.1@7253.22,3326 7721.02,3326 7876.1,3481.07 7876.1,3716.22 7764.2,3828.12 7763.62,3828.12 7761.44,3830.3 U1.1@7651.99,3830.3
  Top Layer w20: R1.2 7185.79,3378.56 R2.1@7240.39,3323.97
SPI1_MISO: P1.7 U1.3 U3.6 | length 1255
  Top Layer w10: U1.3@7649.08,3873.7 7883.3,3873.7 8046.14,3710.86 8084.75,3710.86 P1.7@8205,3710.86 ; P1.7@8205,3711 8283,3711 8466,3894 v3@8569,3894 ; v3(8711.5,3906) U3.6
  Bottom Layer w10: v3(8569,3893) 8698.5,3893 v3(8711.5,3906)
SPI1_MOSI: P1.6 U1.4 U3.5 | length 1216.4
  Top Layer w10: U1.4@7649.08,3893.38 7914.62,3893.38 7997.14,3810.86 8084.75,3810.86 8204.86,3810.86 8205,3811 8234,3811 8453,4030 8642,4030 8686.5,3985.5 U3.5
SPI1_SCK: P1.8 U1.5 U3.4 | length 1456.7
  Top Layer w10: U1.5@7649.08,3913.07 7975.93,3913.07 v1(8025,3864) ; P1.8@8084.75,3610.86 P1.8@8204.86,3610.86 ; P1.8@8205,3611 P1.8@8204.86,3610.86 ; v3(8561,3855.05) 8491.05,3855.05 8246.86,3610.86 P1.8@8204.86,3610.86 ; U3.4 8661.5,3863.5 v3(8669,3856)
  Bottom Layer w10: v1(8025,3864) 8025,3670.61 P1.8@8084.75,3610.86 ; v3(8561,3855.05) v3@8669,3855.05
SWCLK: EV1.2 U3.20 | length 1777
  Top Layer w10: v3(8541,4096) 8754,4096 8786.5,4128.5 U3.20
  Bottom Layer w10: v3(8541,4096) 8532,4087 8532,3841 8548,3825 8548,2944 8734,2758 EV1.2
SWDIO: EV1.3 U3.21 | length 1747
  Top Layer w10: v3(8538,4136) 8544,4130 8744,4130 8761.5,4147.5 U3.21
  Bottom Layer w10: v3(8538,4136) 8510.5,4108.5 8510.5,3826.5 8518,3819 8518,2892 8633,2777 EV1.3@8633,2723
TA: pad.10 U1.2 | length 223.1
  Top Layer w10: U1.2@7649.08,3854.01 7839.76,3854.01 v13(7862.7,3831.09)
TD: T1.1 U1.12 | length 464.8
  Top Layer w10: T1.1 7513,4377 7513,4204 7470.23,4161.23 7470.23,4021.33 7523.09,3968.47 U1.12@7523.09,3960.31
TEST: T2.1 U3.24 | length 350.3
  Top Layer w10: v3(8653,4362) 8686.5,4328.5 U3.24
  Bottom Layer w10: T2.1 8543,4472 v3(8653,4362)
TVDD: C3.1 C4.1 FB1.1 U1.15 | length 505.9
  Top Layer w10: 7350.85,3893.38 U1.15@7495.53,3893.38
  Top Layer w25: C4.1@7311,3833.25 7350.85,3873.1 7350.85,3893.38 C3.1@7350.85,3926.15
  Bottom Layer w25: v9(7396.5,3897.23) 7423.96,3924.69 v9(7423.96,4137.63)
TX1: L2.2 U1.14 | length 303.7
  Top Layer w10: 7456.13,3925.54 7469.04,3912.63 U1.14@7501.62,3912.63
  Top Layer w20: L2.2@7248,4033.54 7348.13,4033.54 7456.13,3925.54
TX2: L1.2 U1.16 | length 334
  Top Layer w10: 7453.71,3860.97 7466.44,3873.7 U1.16@7495.53,3873.7
  Top Layer w20: L1.2@7239.8,3710.54 7239.8,3728.75 L1.2 7286,3734 7365.51,3813.51 7394.51,3813.51 7441.97,3860.97 7453.71,3860.97
V33O: C43.1 U2.3 | length 140.9
  Top Layer w20: C43.1 8731,3467 U2.3
VIN: C5.1 C6.1 FB1.2 J2.2 J3.2 P1.3 | length 2402.9
  Top Layer w30: 7346.13,4249.46 7346.13,4331.13 7465,4450 7683,4450 J2.2 ; FB1.2@7347.08,4139.17 7347.08,4263.22 ; P1.3@8084.75,4110.86 P1.3@8219.86,4110.86 ; P1.3@8205,4111 8381,4111 8457,4187 v5(8457,4574)
  Bottom Layer w30: J2.2 7886,4385 7964,4307 7964,4219 8072.14,4110.86 P1.3@8084.75,4110.86 ; v5(8457,4574) 8457,4956 J3.2
VLDO: C38.2 CE2.1 J3.1 J4.3 U4.3 | length 888.4
  Top Layer w30: J3.1 8664,5063 8890,5063 8938,5015 J4.3 C38.2 8940,4839 CE2.1 9124.43,4839 U4.3
VMID: C12.2 R2.2 U1.24 | length 1113.5
  Top Layer w12: R2.2@7253.95,3382 7734,3382 7845,3493 7845,3712 7760.55,3796.45 7627.55,3796.45 U1.24@7624,3800
VREGIN: J2.1 U1.18 | length 755
  Top Layer w10: 7469.77,3834.02 U1.18
  Top Layer w20: v9(7443.97,3792.5) 7443.97,3808.22 7469.77,3834.02
  Bottom Layer w30: v9(7443.97,3792.5) 7500,3848.53 7500,4036 7648,4184 J2.1
VREGOUT: C7.1 C8.1 J1.1 U1.19 | length 688.7
  Top Layer w20: J1.1 7454,3455 7411,3498 7293,3498 7256,3535 7256,3626.66 7312.34,3683 7334,3683 7356,3683 7369,3696 7417,3696 7519.68,3798.68 U1.19@7519.68,3808.68
VSS: 
VUSB: C36.2 CE1.1 CN1.1 J3.3 R19.1 U4.2 | length 3415
  Top Layer w15: 9481,3786 9488.82,3793.82 CN1.1@9558.65,3793.82
  Top Layer w30: U4.2 9293,4977 9638,4632 9638,4337 R19.1 9538,4213 v5(9481,4156) ; C36.2 9316,3359 CE1.1 9295,3457 9213,3539 v5(9213,3665) 9334,3786 9481,3786
  Bottom Layer w30: J3.3 8464,5063 9001,5063 9085,4979 v5@9159.08,4979 ; v5(9213,3665) 9213,4040 9329,4156 v5(9481,4156)
  other v5: 9159.08,4978
pads on no net: U3.11 U3.16 U3.19 U3.22 U3.23 U3.25 U3.26 U4.0
copper on no net: | length 157.1
  Top Layer w40: 6538.8,4779.49 cw(c6538.8,4679.49) 6638.8,4679.49
  other v4: 8205,2828.85 6757.29,2890.99 8205,3128.85 6757.29,3196.99 6757.29,3505.99 6754.34,4236.3 6758.66,4540 8205,4612.15 6758.66,4840 8205,4912.15
  other v6: 8204.75,3461 8204.75,3561 8204.75,3661 8204.75,3761 8204.75,3861 8204.75,3961 8204.75,4061 8204.75,4161 8204.75,4261
  other v7: 6719.8,3871.86
  other v11: 6758.56,3823.23 6759.36,3923.38
  other v12: 6808.65,3872.04

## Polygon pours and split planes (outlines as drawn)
GND on Top Layer "Top GND" (solid, remove dead copper, pour order 14): 6767.61,4484.38 8059.41,4479.38 8059.41,3263.67 6773.39,3260.77
no net on Top Layer "Bottom Layer-No Net" (solid, remove dead copper, pour order 10): 9477,3794 9478,3793 9520,3793
GND on Top Layer "Bottom GND" (solid, remove dead copper, pour order 13): 8259.94,5124.8 8749.8,5124.49 9726.75,5124.4 9726.75,2585.71 8298.06,2589.56 8266.47,2589.55
GND on Bottom Layer "Bottom Layer-GND" (solid, pour order 9): 8103.64,4047 8175.64,4047 8176.64,4046 8176.64,3971 8174.64,3973 8100.64,3973 8100.64,4047
GND on Bottom Layer "Bottom GND" (solid, remove dead copper, pour order 11): 6767.66,4491.62 8130.49,4486.13 8132.34,3260.79 6770.48,3251.03
GND on Bottom Layer "Bottom GND" (solid, remove dead copper, pour order 12): 8302.84,5132.79 8754.57,5132.49 9731.53,5132.39 9731.53,2593.71 8267,2595 8264,5130
no net on Top Overlay "Bottom Layer-No Net" (solid): 8991,4254 8991,3842 8512,3842 8512,4254
no net on Top Overlay "Bottom Layer-No Net" (solid): 8890,3418 8890,2950 8584,2950 8584,3418

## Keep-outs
Keep-Out Layer:
  lines w8: 9719,2600 9719,5140
  lines w10: 9719,2600 4320,2600 4320,5140 9719,5140
  lines w30: 6751.6,2678.23 6751.6,2800.28 ; 6756.31,4021.73 6756.31,4143.78 ; 6758.66,2992.95 6758.66,3115 ; 6758.66,3288 6758.66,3410.05 ; 6758.66,3597.95 6758.66,3720 ; 6763.37,4937.09 6763.37,5059.14 ; 8205,2664 8205.25,2751 ; 8205,2906 8205.25,3042 ; 8205,3207 8205,3329.05 ; 8205,4392 8205,4537 ; 8205,4696 8205,4829 ; 8205,4999.24 8205,5093 ; 6758.66,4326.85 6758.66,4448.9 6758.66,4326.85 ; 6761.02,4631.97 6761.02,4754.02 6761.02,4631.97

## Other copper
Top Layer:
  rectangle net GND: 8103.18,3973 8262,4046.01
  pour cut-out: 7272,3890.3 7272,3951 7309,3951 7309,3890 7308.1,3889.1
  pour cut-out: 7303.3,3648 7364,3648 7364,3611 7303,3611 7302.1,3611.9
  region net GND: 7507.73,3659.42 7546.41,3659.42 7546.01,3659.01 7545.2,3630 7507.73,3630 7506.12,3631.61 7507.73,3633.22
  region net AVDD: 7507.43,3714.97 7547.65,3714.97 7549.8,3712.82 7549.8,3686 7508.17,3685.95 7508.59,3686.37 7507.97,3689.22
  region net TVDD: 7422.31,3878.55 7362.18,3878.55 7362.08,3878.65 7362.55,3879.12 7362.55,3889.06 7422.36,3889.06 7422.52,3888.9
  region net TVDD: 7422.31,3911.55 7354.34,3911.54 7354.34,3898.25 7422.36,3898.53
  region net TX2: 7450.17,3870.28 7456.46,3869.42 7464.42,3878.34
  region net TX2: 7468.97,3869.35 7462.32,3862.7 7462.06,3855.47
  region net TX1: 7451.71,3916.59 7454.18,3919.07 7456.93,3919.07 7456.93,3917.92 7466.45,3908.39
  pour cut-out: 7456.29,3920.24 7456.32,3920.24 7456.32,3918.83 7456.35,3918.8 7454.85,3918.8
  pour cut-out: 7452.28,3916.35 7454.73,3918.8 7457.59,3918.8 7457.59,3917.83 7457.14,3918.28 7454.33,3918.28 7452.37,3916.32
  region net TX1: 7484.67,3917.4 7471.43,3917.24 7464.67,3923.93 7463.57,3932.16
  region net TVDD: 7422.31,3911.54 7475.31,3894.84 7432.16,3894.84 7430.71,3893.38 7476.31,3893.38 7422.31,3878.54
  region net VREGIN: 7496.04,3838.94 7475.84,3839.03 7470.3,3844.03
  region net VREGIN: 7476.79,3827.02 7478.86,3829.09 7478.86,3831.52
  pour cut-out: 7380,4190.3 7380,4251 7417,4251 7417,4190 7416.1,4189.1
Bottom Layer:
  rectangle net GND: 8174,3973 8266,4047
  region net TVDD: 7422.31,3895.04 7436,3922 7389.12,3903.75 7387.66,3902.29 7412,3931 7386,3921 7372.82,3893.89

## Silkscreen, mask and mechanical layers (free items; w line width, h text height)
Top Overlay:
  drawing of 35 lines, arcs and shapes, not listed
  text "VDD" at 8802,5066 h30
  text "LDO" at 8919,5066 h30
  text "3V3" at 8683,5065 h30
  text "LDO" at 8561,5063 h30
  text "VUSB" at 8310,5061 h30
  text "Vin" at 8454,5057 h30
  text "POWER" at 8499,4809 h30
  text "ACTIVE" at 8688,4809 h30
  text "RSTPD" at 7911,4299 h23
  text "VREGNIN" at 7557,4294 h20
  text "VIN" at 7750,4284 h30
  text "VDDIO" at 7911,4192 h23
  text "Vin" at 7930,4091 h30
  text "GND" at 7934,4008 h30
  text "NCS" at 7925.83,3900.1 h30
  text "MOSI" at 7920.75,3800.86 h25
  text "MISO" at 7914.75,3694.86 h25
  text "SCLK" at 7909.75,3602.86 h25
  text "IRQ" at 7927.8,3495.57 h30
  text "3V3" at 7922.88,3399.11 h30
  text "VREGOUT" at 7365,3330 h20
  text "3V3" at 7549,3326 h30
  text "Antenna_(57x47mm)" at 6694.8,3046.99 h30 r90
  text "BC45B4523" at 7138,3017 h60
  text "NFC READER" at 7144,2914 h60
  text "Develop Board" at 7138,2825 h60
  text "GND" at 8454,2798 h35 r90
  text "NRST" at 8551,2798 h35 r90
  text "SWDIO" at 8652,2796 h30 r90
  text "SWCLK" at 8754,2795 h30 r90
  text "MVDD" at 8848,2793 h30 r90
  text "Ver10 20190214" at 7140,2718 h45
Bottom Overlay:
  circle w68.9: c5534.8,3871.99 r34.49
